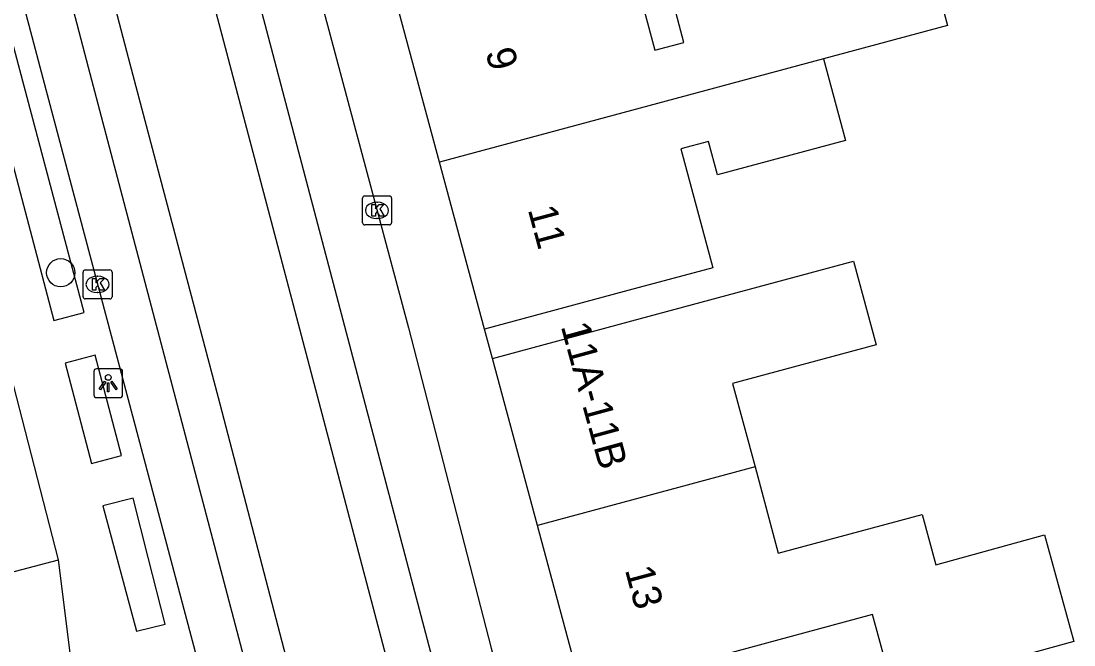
# Model space of a CAD drawing. Extents: x 159377 to 159983, y 382996 to 383595.
# Drawn here: x 159689.56 to 159725.98, y 383336.72 to 383358.29 of the extents above; entities that cross this region are included whole.
import ezdxf

# ---------------------------------------------------------------- set-up
doc = ezdxf.new("R2010")
doc.units = 0
for name, color, linetype in [('IMGEO_Boom', 7, 'Continuous'), ('IMGEO_Kolk', 7, 'Continuous'), ('IMGEO_Lichtpunt', 7, 'Continuous'), ('IMGEO_Pand', 7, 'Continuous'), ('IMGEO_Pand_nummerreeks', 7, 'Continuous'), ('IMGEO_Rijbaan_lokaal_gesloten', 7, 'Continuous'), ('IMGEO_Voetpad_open', 7, 'Continuous')]:
    doc.layers.add(name, color=color, linetype=linetype)

msp = doc.modelspace()

# ---------------------------------------------------------------- linework, layer by layer
at = {"layer": 'IMGEO_Boom'}
msp.add_circle((159690.933, 383349.586), 0.489, dxfattribs=at)
at = {"layer": 'IMGEO_Kolk'}
for p, q in [((159701.374, 383351.315), (159701.374, 383352.167)), ((159701.449, 383352.241), (159702.301, 383352.241)), ((159702.375, 383352.167), (159702.375, 383351.315)), ((159701.862, 383352.021), (159701.887, 383352.021)), ((159701.885, 383351.461), (159701.86, 383351.461)), ((159702.301, 383351.241), (159701.449, 383351.241)), ((159691.706, 383348.756), (159691.706, 383349.608)), ((159691.781, 383349.682), (159692.633, 383349.682)), ((159692.707, 383349.608), (159692.707, 383348.756)), ((159692.194, 383349.462), (159692.219, 383349.462)), ((159692.217, 383348.902), (159692.192, 383348.902)), ((159692.633, 383348.682), (159691.781, 383348.682))]:
    msp.add_line(p, q, dxfattribs=at)
for points in [[(159701.374, 383351.315), (159701.374, 383352.167)], [(159701.449, 383352.241), (159702.301, 383352.241)], [(159702.375, 383352.167), (159702.375, 383351.315)], [(159701.695, 383351.941), (159701.818, 383351.941), (159701.818, 383351.79), (159701.948, 383351.941), (159702.112, 383351.941), (159701.966, 383351.79), (159702.119, 383351.541), (159701.967, 383351.541), (159701.882, 383351.705), (159701.818, 383351.638), (159701.818, 383351.541), (159701.695, 383351.541), (159701.695, 383351.941)], [(159702.301, 383351.241), (159701.449, 383351.241)], [(159691.706, 383348.756), (159691.706, 383349.608)], [(159691.781, 383349.682), (159692.633, 383349.682)], [(159692.707, 383349.608), (159692.707, 383348.756)], [(159692.027, 383349.382), (159692.15, 383349.382), (159692.15, 383349.231), (159692.28, 383349.382), (159692.444, 383349.382), (159692.298, 383349.231), (159692.451, 383348.982), (159692.299, 383348.982), (159692.214, 383349.146), (159692.15, 383349.079), (159692.15, 383348.982), (159692.027, 383348.982), (159692.027, 383349.382)], [(159692.633, 383348.682), (159691.781, 383348.682)]]:
    msp.add_lwpolyline(points, dxfattribs=at)
for centre, start, end in [((159701.451, 383352.165), 91.552, 178.448), ((159701.451, 383352.165), 91.552, 178.448), ((159702.299, 383352.165), 1.552, 88.448), ((159702.299, 383352.165), 1.552, 88.448), ((159701.451, 383351.317), 181.552, 268.448), ((159701.451, 383351.317), 181.552, 268.448), ((159702.299, 383351.317), 271.552, 358.448), ((159702.299, 383351.317), 271.552, 358.448), ((159691.783, 383349.606), 91.552, 178.448), ((159691.783, 383349.606), 91.552, 178.448), ((159692.631, 383349.606), 1.552, 88.448), ((159692.631, 383349.606), 1.552, 88.448), ((159691.783, 383348.758), 181.552, 268.448), ((159691.783, 383348.758), 181.552, 268.448), ((159692.631, 383348.758), 271.552, 358.448), ((159692.631, 383348.758), 271.552, 358.448)]:
    msp.add_arc(centre, 0.0765, start, end, dxfattribs=at)
for centre, major_axis, ratio, start_param, end_param in [((159701.861, 383351.741), (-0.387, 0.002), 0.722429, 4.712389, 7.853982), ((159701.886, 383351.741), (-0.39, 0.002), 0.717154, 1.570796, 4.712389), ((159692.193, 383349.182), (-0.387, 0.002), 0.722429, 4.712389, 7.853982), ((159692.218, 383349.182), (-0.39, 0.002), 0.717154, 1.570796, 4.712389)]:
    msp.add_ellipse(centre, major_axis=major_axis, ratio=ratio, start_param=start_param, end_param=end_param, dxfattribs=at)
at = {"layer": 'IMGEO_Lichtpunt'}
for p, q in [((159692.077, 383346.168), (159692.077, 383345.361)), ((159692.077, 383346.168), (159692.077, 383345.361)), ((159692.979, 383346.263), (159692.171, 383346.263)), ((159692.979, 383346.263), (159692.171, 383346.263)), ((159693.073, 383345.361), (159693.073, 383346.168)), ((159693.073, 383345.361), (159693.073, 383346.168)), ((159692.171, 383345.267), (159692.979, 383345.267)), ((159692.171, 383345.267), (159692.979, 383345.267))]:
    msp.add_line(p, q, dxfattribs=at)
for points in [[(159692.451, 383345.832), (159692.49, 383345.804), (159692.302, 383345.542), (159692.264, 383345.569), (159692.451, 383345.832)], [(159692.553, 383345.784), (159692.6, 383345.784), (159692.6, 383345.462), (159692.553, 383345.462), (159692.553, 383345.784)], [(159692.663, 383345.804), (159692.701, 383345.831), (159692.888, 383345.569), (159692.849, 383345.541), (159692.663, 383345.804)]]:
    msp.add_lwpolyline(points, dxfattribs=at)
msp.add_circle((159692.576, 383345.966), 0.0994, dxfattribs=at)
for centre, start, end in [((159692.171, 383346.168), 90, 180), ((159692.171, 383346.168), 90, 180), ((159692.979, 383346.168), 0, 90), ((159692.979, 383346.168), 0, 90), ((159692.171, 383345.361), 180, 270), ((159692.171, 383345.361), 180, 270), ((159692.979, 383345.361), 270, 0), ((159692.979, 383345.361), 270, 360)]:
    msp.add_arc(centre, 0.0946, start, end, dxfattribs=at)
at = {"layer": 'IMGEO_Pand'}
for points in [[(159690.86, 383339.654), (159688.157, 383350.102), (159686.767, 383355.473), (159685.743, 383359.431), (159683.326, 383368.772), (159680.913, 383378.095), (159678.706, 383386.624)], [(159702.478, 383359.191), (159707.306, 383360.492), (159710.4, 383361.325), (159711.489, 383357.283), (159712.485, 383357.551), (159712.159, 383358.763), (159720.808, 383361.092), (159721.603, 383358.136), (159717.318, 383356.983)], [(159704.034, 383353.41), (159702.478, 383359.191)], [(159717.318, 383356.983), (159704.034, 383353.41)], [(159717.318, 383356.983), (159718.079, 383354.158), (159713.651, 383352.966), (159713.339, 383354.126), (159712.378, 383353.868), (159713.485, 383349.757), (159710.419, 383348.931), (159705.59, 383347.631)], [(159705.59, 383347.631), (159704.034, 383353.41)], [(159705.865, 383346.625), (159710.693, 383347.925), (159718.36, 383349.99), (159719.14, 383347.093), (159714.176, 383345.756), (159714.953, 383342.87)], [(159707.422, 383340.842), (159705.865, 383346.625)], [(159714.953, 383342.87), (159707.422, 383340.842)], [(159714.953, 383342.87), (159715.756, 383339.888), (159720.737, 383341.229), (159721.207, 383339.481), (159724.964, 383340.52), (159725.982, 383336.838), (159719.743, 383335.112), (159719.014, 383337.764), (159713.808, 383336.362), (159708.979, 383335.062)], [(159708.979, 383335.062), (159707.422, 383340.842)], [(159680.855, 383337.044), (159681.087, 383337.105), (159686.022, 383338.392), (159688.088, 383338.931), (159690.86, 383339.654)]]:
    msp.add_lwpolyline(points, dxfattribs=at)
at = {"layer": 'IMGEO_Rijbaan_lokaal_gesloten'}
for points in [[(159706.907, 383324.871), (159703.844, 383336.06), (159696.414, 383364.212), (159689.359, 383390.944), (159681.054, 383422.407), (159675.902, 383441.929), (159673.093, 383452.571), (159671.587, 383458.28)], [(159670.094, 383457.885), (159670.625, 383455.872), (159678.409, 383426.38), (159686.465, 383395.857), (159692.786, 383371.909), (159698.534, 383350.133), (159705.315, 383324.44), (159706.001, 383324.626), (159706.907, 383324.871)], [(159700.731, 383323.191), (159702.049, 383323.57), (159696.447, 383345.036), (159693.274, 383357.013), (159667.185, 383456.552), (159667.027, 383457.076)], [(159700.731, 383323.191), (159691.898, 383356.687), (159665.691, 383456.728)]]:
    msp.add_lwpolyline(points, dxfattribs=at)
at = {"layer": 'IMGEO_Voetpad_open'}
for points in [[(159663.864, 383456.282), (159664.964, 383452.218), (159665.106, 383451.555), (159670.1, 383433.187), (159678.787, 383399.561), (159682.877, 383384.322), (159688.475, 383363.216), (159690.31, 383356.311), (159696.363, 383333.532), (159698.5, 383325.536), (159698.524, 383325.331)], [(159690.128, 383395.731), (159695.004, 383377.404), (159700.034, 383358.613), (159702.961, 383347.681), (159705.825, 383336.598), (159706.48, 383334.224)], [(159688.224, 383357.272), (159690.694, 383347.929), (159691.743, 383348.213), (159689.269, 383357.553), (159688.224, 383357.272)], [(159705.865, 383346.625), (159705.59, 383347.631)], [(159691.082, 383346.462), (159691.999, 383342.99), (159693.03, 383343.27), (159692.119, 383346.736), (159691.082, 383346.462)], [(159692.387, 383341.526), (159693.555, 383337.186), (159694.542, 383337.432), (159693.956, 383339.742), (159693.436, 383341.792), (159692.387, 383341.526)], [(159691.725, 383332.764), (159690.86, 383339.654)]]:
    msp.add_lwpolyline(points, dxfattribs=at)

# ---------------------------------------------------------------- texts
at = {"layer": 'IMGEO_Pand_nummerreeks'}
for s, rotation, p in [('9', 285.0628, (159705.618, 383357.221)), ('11', 285.0686, (159707.084, 383351.775)), ('11A-11B', 285.2551, (159708.226, 383347.737)), ('13', 285.0763, (159710.443, 383339.317))]:
    msp.add_text(s, height=1, rotation=rotation, dxfattribs=at).set_placement(p)

doc.saveas('drawing.dxf')
